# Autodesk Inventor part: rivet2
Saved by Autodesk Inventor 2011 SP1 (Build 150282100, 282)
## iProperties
Created: 2010-12
Part Number: rivet2
Document SubType Name: Modeling
Designer: eric
Density: 1 g/cm^3
Author: eric
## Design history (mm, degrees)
feature "Base1"
node "Solide1"
node "Corps solides"
node "Corps surfaciques"
